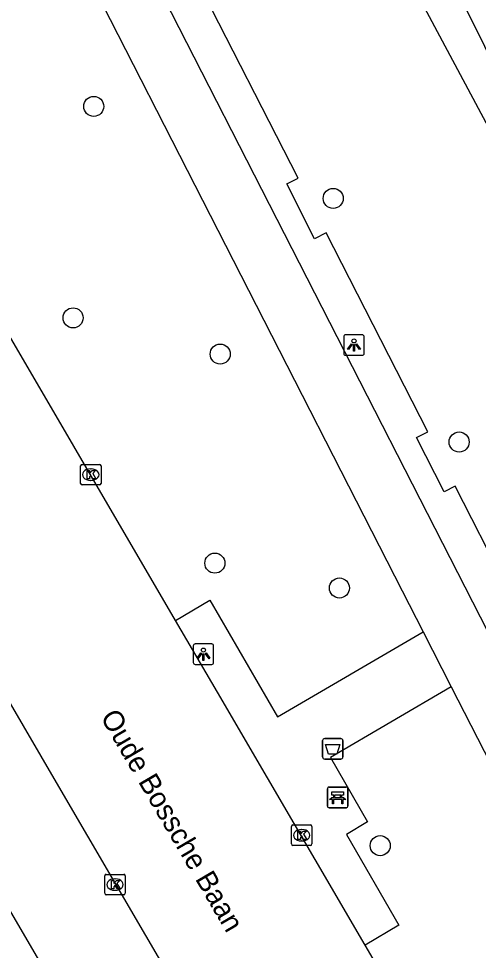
# Model space of a CAD drawing. Extents: x 159353 to 160616, y 385893 to 387321.
# Drawn here: x 159867.44 to 159889.87, y 386362.16 to 386407.58 of the extents above; entities that cross this region are included whole.
import ezdxf

# ---------------------------------------------------------------- set-up
doc = ezdxf.new("R2010")
doc.units = 0
for name, color, linetype in [('IMGEO_Afvalbak', 7, 'Continuous'), ('IMGEO_Bank', 7, 'Continuous'), ('IMGEO_Boom', 7, 'Continuous'), ('IMGEO_Fietspad_gesloten', 7, 'Continuous'), ('IMGEO_Groenvoorziening', 7, 'Continuous'), ('IMGEO_Kolk', 7, 'Continuous'), ('IMGEO_Lichtpunt', 7, 'Continuous'), ('IMGEO_Openbare_ruimte_label', 7, 'Continuous'), ('IMGEO_Rijbaan_lokaal_gesloten', 7, 'Continuous'), ('IMGEO_Voetpad_open', 7, 'Continuous'), ('IMGEO_Waterloop', 7, 'Continuous')]:
    doc.layers.add(name, color=color, linetype=linetype)

msp = doc.modelspace()

# ---------------------------------------------------------------- linework, layer by layer
at = {"layer": 'IMGEO_Afvalbak'}
for p, q in [((159882.373, 386372.484), (159883.163, 386372.484)), ((159883.163, 386372.484), (159882.373, 386372.484)), ((159882.273, 386371.584), (159882.273, 386372.384)), ((159882.273, 386372.384), (159882.273, 386371.584)), ((159883.263, 386372.384), (159883.263, 386371.584)), ((159883.263, 386371.584), (159883.263, 386372.384)), ((159883.163, 386371.484), (159882.373, 386371.484)), ((159882.373, 386371.484), (159883.163, 386371.484))]:
    msp.add_line(p, q, dxfattribs=at)
msp.add_lwpolyline([(159882.416, 386372.198), (159883.12, 386372.198), (159882.971, 386371.728), (159882.565, 386371.728), (159882.416, 386372.198)], dxfattribs=at)
for centre, start, end in [((159882.373, 386372.384), 90, 180), ((159882.373, 386372.384), 90, 180), ((159883.163, 386372.384), 0, 90), ((159883.163, 386372.384), 360, 90), ((159882.373, 386371.584), 180, 270), ((159882.373, 386371.584), 180, 270), ((159883.163, 386371.584), 270, 0), ((159883.163, 386371.584), 270, 0)]:
    msp.add_arc(centre, 0.1, start, end, dxfattribs=at)
at = {"layer": 'IMGEO_Bank'}
for p, q in [((159882.506, 386369.187), (159882.506, 386370.028)), ((159882.506, 386370.028), (159882.506, 386369.187)), ((159882.581, 386370.112), (159883.422, 386370.112)), ((159883.422, 386370.112), (159882.581, 386370.112)), ((159882.815, 386369.618), (159882.815, 386369.724)), ((159882.859, 386369.724), (159882.859, 386369.618)), ((159883.147, 386369.73), (159882.865, 386369.73)), ((159883.153, 386369.618), (159883.153, 386369.724)), ((159883.197, 386369.724), (159883.197, 386369.618)), ((159883.506, 386370.037), (159883.506, 386369.196)), ((159883.506, 386369.196), (159883.506, 386370.037)), ((159883.203, 386369.51), (159882.81, 386369.51)), ((159882.865, 386369.612), (159883.147, 386369.612)), ((159883.431, 386369.112), (159882.59, 386369.112)), ((159882.59, 386369.112), (159883.431, 386369.112))]:
    msp.add_line(p, q, dxfattribs=at)
for points in [[(159882.809, 386369.73), (159882.723, 386369.73), (159882.723, 386369.891), (159883.286, 386369.891), (159883.286, 386369.73), (159883.203, 386369.73)], [(159882.753, 386369.51), (159882.611, 386369.51), (159882.723, 386369.612), (159882.809, 386369.612)], [(159882.803, 386369.503), (159882.803, 386369.296), (159882.76, 386369.296), (159882.76, 386369.503)], [(159883.203, 386369.612), (159883.286, 386369.612), (159883.398, 386369.51), (159883.259, 386369.51)], [(159883.253, 386369.503), (159883.253, 386369.296), (159883.209, 386369.296), (159883.209, 386369.503)]]:
    msp.add_lwpolyline(points, dxfattribs=at)
for centre, radius, start, end in [((159882.584, 386370.034), 0.0779, 92.4484, 184.2845), ((159882.584, 386370.034), 0.0779, 92.4484, 184.2845), ((159882.808, 386369.723), 0.00671, 2.8957, 87.1043), ((159882.865, 386369.723), 0.00671, 92.8957, 177.1043), ((159883.147, 386369.723), 0.00671, 2.8957, 87.1043), ((159883.204, 386369.723), 0.00671, 92.8957, 177.1043), ((159883.428, 386370.034), 0.0779, 2.4484, 94.2845), ((159883.428, 386370.034), 0.0779, 2.4484, 94.2845), ((159882.753, 386369.503), 0.00671, 2.8957, 87.1043), ((159882.81, 386369.503), 0.00671, 92.8957, 177.1043), ((159882.808, 386369.619), 0.00671, 272.8957, 357.1043), ((159882.865, 386369.619), 0.00671, 182.8957, 267.1043), ((159883.147, 386369.619), 0.00671, 272.8957, 357.1043), ((159883.204, 386369.619), 0.00671, 182.8957, 267.1043), ((159883.202, 386369.503), 0.00671, 2.8957, 87.1043), ((159883.259, 386369.503), 0.00671, 92.8957, 177.1043), ((159882.584, 386369.19), 0.0779, 182.4484, 274.2845), ((159882.584, 386369.19), 0.0779, 182.4484, 274.2845), ((159883.428, 386369.19), 0.0779, 272.4484, 4.2845), ((159883.428, 386369.19), 0.0779, 272.4484, 4.2845)]:
    msp.add_arc(centre, radius, start, end, dxfattribs=at)
at = {"layer": 'IMGEO_Boom'}
for centre in [(159871.104, 386403.307), (159882.789, 386398.82), (159870.096, 386392.993), (159877.275, 386391.231), (159888.934, 386386.941), (159877.015, 386381.036), (159883.092, 386379.823), (159885.084, 386367.26)]:
    msp.add_circle(centre, 0.489, dxfattribs=at)
at = {"layer": 'IMGEO_Fietspad_gesloten'}
for points in [[(159969.484, 386232.379), (159951.117, 386263.827), (159929.119, 386301.905), (159889.595, 386379.139), (159865.341, 386426.534), (159857.571, 386441.898), (159857.138, 386442.747)], [(159861.4, 386428.071), (159886.153, 386379.68), (159887.174, 386377.69)], [(159947.456, 386226.623), (159938.723, 386241.317), (159864.988, 386367.537), (159851.28, 386391.003)], [(159887.174, 386377.69), (159888.551, 386375.008)], [(159888.551, 386375.008), (159928.011, 386298.139), (159962.321, 386239.14)]]:
    msp.add_lwpolyline(points, dxfattribs=at)
at = {"layer": 'IMGEO_Groenvoorziening'}
msp.add_lwpolyline([(159871.801, 386436.983), (159897.511, 386388.928), (159899.33, 386389.902), (159901.616, 386391.127), (159897.327, 386400.822), (159898.04, 386408.508), (159889.685, 386419.762)], dxfattribs=at)
at = {"layer": 'IMGEO_Kolk'}
for p, q in [((159870.46, 386384.924), (159870.46, 386385.776)), ((159870.535, 386385.85), (159871.387, 386385.85)), ((159870.948, 386385.63), (159870.973, 386385.63)), ((159871.461, 386385.776), (159871.461, 386384.924)), ((159871.387, 386384.85), (159870.535, 386384.85)), ((159870.971, 386385.07), (159870.946, 386385.07)), ((159880.75, 386367.342), (159880.75, 386368.194)), ((159880.825, 386368.268), (159881.677, 386368.268)), ((159881.238, 386368.048), (159881.263, 386368.048)), ((159881.751, 386368.194), (159881.751, 386367.342)), ((159881.261, 386367.488), (159881.236, 386367.488)), ((159881.677, 386367.268), (159880.825, 386367.268)), ((159871.642, 386364.936), (159871.642, 386365.788)), ((159871.717, 386365.862), (159872.569, 386365.862)), ((159872.13, 386365.642), (159872.155, 386365.642)), ((159872.643, 386365.788), (159872.643, 386364.936)), ((159872.569, 386364.862), (159871.717, 386364.862)), ((159872.153, 386365.082), (159872.128, 386365.082))]:
    msp.add_line(p, q, dxfattribs=at)
for points in [[(159870.46, 386384.924), (159870.46, 386385.776)], [(159870.535, 386385.85), (159871.387, 386385.85)], [(159871.461, 386385.776), (159871.461, 386384.924)], [(159870.781, 386385.55), (159870.904, 386385.55), (159870.904, 386385.399), (159871.034, 386385.55), (159871.198, 386385.55), (159871.052, 386385.399), (159871.205, 386385.15), (159871.053, 386385.15), (159870.968, 386385.314), (159870.904, 386385.247), (159870.904, 386385.15), (159870.781, 386385.15), (159870.781, 386385.55)], [(159871.387, 386384.85), (159870.535, 386384.85)], [(159880.75, 386367.342), (159880.75, 386368.194)], [(159880.825, 386368.268), (159881.677, 386368.268)], [(159881.071, 386367.968), (159881.194, 386367.968), (159881.194, 386367.817), (159881.324, 386367.968), (159881.488, 386367.968), (159881.342, 386367.817), (159881.495, 386367.568), (159881.343, 386367.568), (159881.258, 386367.732), (159881.194, 386367.665), (159881.194, 386367.568), (159881.071, 386367.568), (159881.071, 386367.968)], [(159881.751, 386368.194), (159881.751, 386367.342)], [(159881.677, 386367.268), (159880.825, 386367.268)], [(159871.642, 386364.936), (159871.642, 386365.788)], [(159871.717, 386365.862), (159872.569, 386365.862)], [(159872.643, 386365.788), (159872.643, 386364.936)], [(159871.963, 386365.562), (159872.086, 386365.562), (159872.086, 386365.411), (159872.216, 386365.562), (159872.38, 386365.562), (159872.234, 386365.411), (159872.387, 386365.162), (159872.235, 386365.162), (159872.15, 386365.326), (159872.086, 386365.259), (159872.086, 386365.162), (159871.963, 386365.162), (159871.963, 386365.562)], [(159872.569, 386364.862), (159871.717, 386364.862)]]:
    msp.add_lwpolyline(points, dxfattribs=at)
for centre, start, end in [((159870.537, 386385.774), 91.552, 178.448), ((159870.537, 386385.774), 91.552, 178.448), ((159871.385, 386385.774), 1.552, 88.448), ((159871.385, 386385.774), 1.552, 88.448), ((159870.537, 386384.926), 181.552, 268.448), ((159870.537, 386384.926), 181.552, 268.448), ((159871.385, 386384.926), 271.552, 358.448), ((159871.385, 386384.926), 271.552, 358.448), ((159880.827, 386368.192), 91.552, 178.448), ((159880.827, 386368.192), 91.552, 178.448), ((159881.675, 386368.192), 1.552, 88.448), ((159881.675, 386368.192), 1.552, 88.448), ((159880.827, 386367.344), 181.552, 268.448), ((159880.827, 386367.344), 181.552, 268.448), ((159881.675, 386367.344), 271.552, 358.448), ((159881.675, 386367.344), 271.552, 358.448), ((159871.719, 386365.786), 91.552, 178.448), ((159871.719, 386365.786), 91.552, 178.448), ((159872.567, 386365.786), 1.552, 88.448), ((159872.567, 386365.786), 1.552, 88.448), ((159871.719, 386364.938), 181.552, 268.448), ((159871.719, 386364.938), 181.552, 268.448), ((159872.567, 386364.938), 271.552, 358.448), ((159872.567, 386364.938), 271.552, 358.448)]:
    msp.add_arc(centre, 0.0765, start, end, dxfattribs=at)
for centre, major_axis, ratio, start_param, end_param in [((159870.947, 386385.35), (-0.387, 0.002), 0.722429, 4.712389, 7.853982), ((159870.972, 386385.35), (-0.39, 0.002), 0.717154, 1.570796, 4.712389), ((159881.237, 386367.768), (-0.387, 0.002), 0.722429, 4.712389, 7.853982), ((159881.262, 386367.768), (-0.39, 0.002), 0.717154, 1.570796, 4.712389), ((159872.129, 386365.362), (-0.387, 0.002), 0.722429, 4.712389, 7.853982), ((159872.154, 386365.362), (-0.39, 0.002), 0.717154, 1.570796, 4.712389)]:
    msp.add_ellipse(centre, major_axis=major_axis, ratio=ratio, start_param=start_param, end_param=end_param, dxfattribs=at)
at = {"layer": 'IMGEO_Lichtpunt'}
for p, q in [((159883.304, 386392.072), (159883.304, 386391.265)), ((159883.304, 386392.072), (159883.304, 386391.265)), ((159884.206, 386392.167), (159883.398, 386392.167)), ((159884.206, 386392.167), (159883.398, 386392.167)), ((159884.3, 386391.265), (159884.3, 386392.072)), ((159884.3, 386391.265), (159884.3, 386392.072)), ((159883.398, 386391.171), (159884.206, 386391.171)), ((159883.398, 386391.171), (159884.206, 386391.171)), ((159875.959, 386376.998), (159875.959, 386376.191)), ((159875.959, 386376.998), (159875.959, 386376.191)), ((159876.861, 386377.093), (159876.053, 386377.093)), ((159876.861, 386377.093), (159876.053, 386377.093)), ((159876.955, 386376.191), (159876.955, 386376.998)), ((159876.955, 386376.191), (159876.955, 386376.998)), ((159876.053, 386376.097), (159876.861, 386376.097)), ((159876.053, 386376.097), (159876.861, 386376.097))]:
    msp.add_line(p, q, dxfattribs=at)
for points in [[(159883.678, 386391.736), (159883.717, 386391.708), (159883.529, 386391.446), (159883.491, 386391.473), (159883.678, 386391.736)], [(159883.78, 386391.688), (159883.827, 386391.688), (159883.827, 386391.366), (159883.78, 386391.366), (159883.78, 386391.688)], [(159883.89, 386391.708), (159883.928, 386391.735), (159884.115, 386391.473), (159884.076, 386391.445), (159883.89, 386391.708)], [(159876.333, 386376.662), (159876.372, 386376.634), (159876.184, 386376.372), (159876.146, 386376.399), (159876.333, 386376.662)], [(159876.435, 386376.614), (159876.482, 386376.614), (159876.482, 386376.292), (159876.435, 386376.292), (159876.435, 386376.614)], [(159876.545, 386376.634), (159876.583, 386376.661), (159876.77, 386376.399), (159876.731, 386376.371), (159876.545, 386376.634)]]:
    msp.add_lwpolyline(points, dxfattribs=at)
for centre in [(159883.803, 386391.87), (159876.458, 386376.796)]:
    msp.add_circle(centre, 0.0994, dxfattribs=at)
for centre, start, end in [((159883.398, 386392.072), 90, 180), ((159883.398, 386392.072), 90, 180), ((159884.206, 386392.072), 0, 90), ((159884.206, 386392.072), 0, 90), ((159883.398, 386391.265), 180, 270), ((159883.398, 386391.265), 180, 270), ((159884.206, 386391.265), 270, 0), ((159884.206, 386391.265), 270, 360), ((159876.053, 386376.998), 90, 180), ((159876.053, 386376.998), 90, 180), ((159876.861, 386376.998), 0, 90), ((159876.861, 386376.998), 0, 90), ((159876.053, 386376.191), 180, 270), ((159876.053, 386376.191), 180, 270), ((159876.861, 386376.191), 270, 0), ((159876.861, 386376.191), 270, 360)]:
    msp.add_arc(centre, 0.0946, start, end, dxfattribs=at)
at = {"layer": 'IMGEO_Rijbaan_lokaal_gesloten'}
for points in [[(159875.1, 386378.233), (159860.078, 386403.938), (159849.792, 386421.291)], [(159858.158, 386389.37), (159869.39, 386370.145), (159949.928, 386232.299)], [(159884.352, 386362.407), (159877.142, 386374.74), (159875.1, 386378.233)], [(159957.867, 386236.533), (159884.352, 386362.407)]]:
    msp.add_lwpolyline(points, dxfattribs=at)
at = {"layer": 'IMGEO_Voetpad_open'}
for points in [[(159891.172, 386380.045), (159888.747, 386384.795), (159888.2, 386384.515), (159886.848, 386387.155), (159887.399, 386387.437), (159882.445, 386397.133), (159881.883, 386396.849), (159880.525, 386399.537), (159881.073, 386399.814), (159876.144, 386409.444), (159875.594, 386409.167), (159874.241, 386411.855), (159874.77, 386412.13), (159870.307, 386420.849), (159869.762, 386420.592), (159868.367, 386423.245), (159868.904, 386423.524), (159864.006, 386433.182), (159863.478, 386432.889), (159862.48, 386434.87), (159862.985, 386435.144), (159859.683, 386441.676), (159858.062, 386444.883)], [(159875.1, 386378.233), (159876.762, 386379.225), (159880.069, 386373.543), (159887.174, 386377.69)], [(159888.551, 386375.008), (159882.658, 386371.566), (159884.456, 386368.425), (159883.438, 386367.811), (159885.997, 386363.384), (159884.352, 386362.407)]]:
    msp.add_lwpolyline(points, dxfattribs=at)
at = {"layer": 'IMGEO_Waterloop'}
msp.add_lwpolyline([(159875.6, 386443.098), (159885.26, 386445.864), (159887.983, 386446.034), (159889.686, 386445.098), (159889.643, 386443.098), (159887.047, 386438.247), (159885.558, 386433.353), (159884.154, 386429.864), (159883.6, 386425.013), (159885.898, 386418.928), (159891.175, 386410.353), (159893.175, 386408.523), (159893.877, 386406.864), (159894.6, 386401.055), (159899.154, 386391.694), (159897.792, 386390.928), (159873.898, 386439.055), (159873.686, 386441.289), (159875.6, 386443.098)], dxfattribs=at)

# ---------------------------------------------------------------- texts
at = {"layer": 'IMGEO_Openbare_ruimte_label'}
msp.add_text('Oude Bossche Baan', height=1, rotation=300.3842, dxfattribs=at).set_placement((159871.406, 386373.534))

doc.saveas('drawing.dxf')
